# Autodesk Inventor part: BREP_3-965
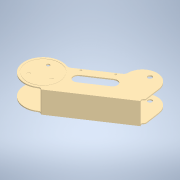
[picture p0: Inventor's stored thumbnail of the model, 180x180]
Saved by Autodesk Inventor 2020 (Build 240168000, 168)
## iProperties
Created: 2017-09
Part Number: BREP_3-965
Material: Or
Document SubType Name: Modeling
Designer: bruno
Density: 19.3 g/cm^3
Appearance: Bleu ciel foncé
Mass: 499.179 g
Surface Area: 276.724 cm^2
Volume: 25.8642 cm^3
Sending System: SolidWorks 2016
Last Author: Prof
Last Saved: 2018-10-03
Author: bruno
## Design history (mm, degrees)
node "Enlèv. mat.-Extru.2"
sketch "Esquisse1"
  geometry: L1 (-67.999, -15.118)-(167.417, -15.118); L2 (167.417, -15.118)-(167.417, 60.72); L3 (167.417, 60.72)-(-67.999, 60.72); L4 (-67.999, 60.72)-(-67.999, -15.118); 1 further point
  constraints: 8 end point, 2 parallel, 1 horizontal, 1 perpendicular
extrude "Extrusion1" cut sketch "Esquisse1" distance "d0" = 100; taper "d1" = 0 deg
node "Solide1"
